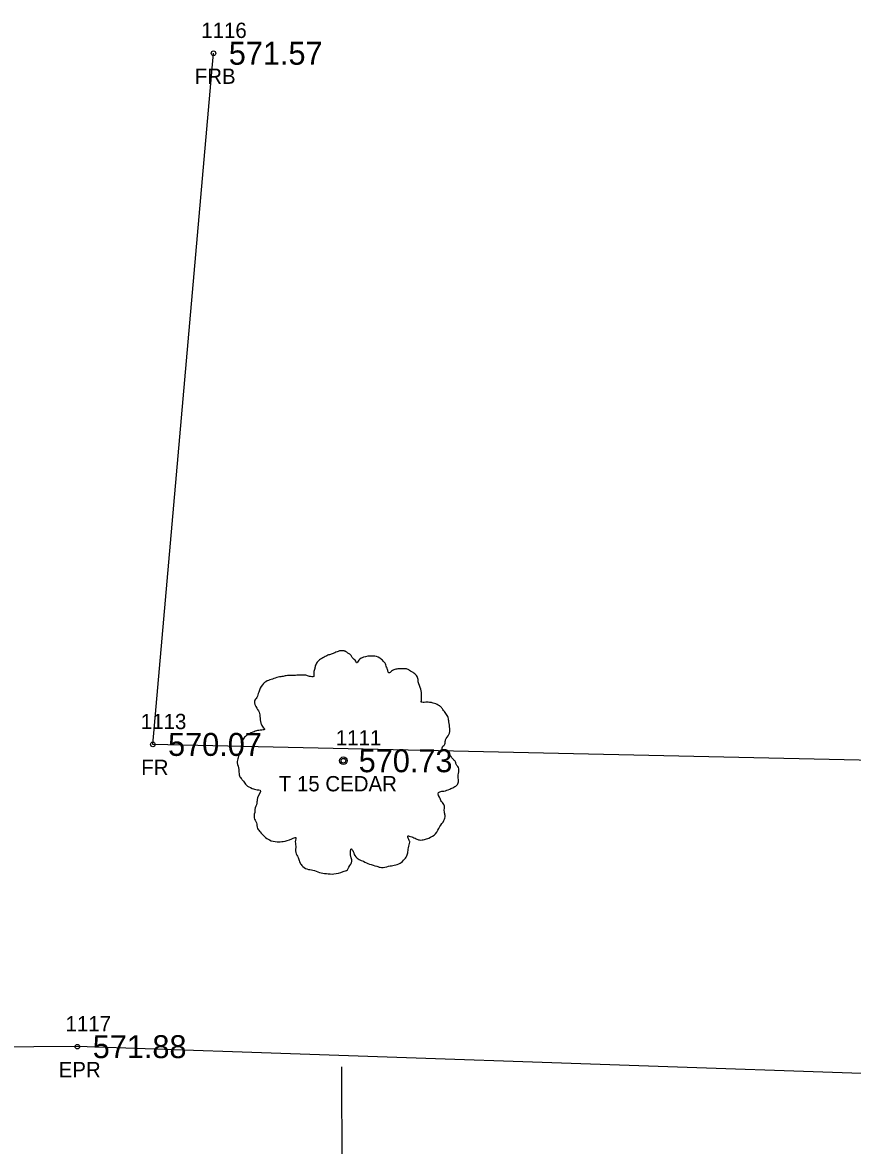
# Model space of a CAD drawing. Extents: x 1529475 to 1532053, y 876698 to 877911.
# Drawn here: x 1531129 to 1531183.3, y 877286.3 to 877359.7 of the extents above; entities that cross this region are included whole.
import ezdxf

# ---------------------------------------------------------------- set-up
doc = ezdxf.new("R2010")
doc.units = 0
for name, color, linetype in [('RD_EX_Fence_Other', 7, 'Continuous'), ('RD_EX_Fence_Other_txCode', 7, 'Continuous'), ('RD_EX_Road', 7, 'Continuous'), ('RD_EX_Road_txCode', 7, 'Continuous'), ('RD_EX_TX_Fence_Other_ELEV', 7, 'Continuous'), ('RD_EX_TX_Road_ELEV', 7, 'Continuous'), ('RD_EX_TX_VEG_ELEV', 7, 'Continuous'), ('RD_EX_VEG', 7, 'Continuous'), ('RD_EX_VEG_txCode', 7, 'Continuous'), ('RD_HC_Data_Tic', 7, 'Continuous'), ('RD_SMD_Locator', 7, 'Continuous')]:
    doc.layers.add(name, color=color, linetype=linetype)

msp = doc.modelspace()

# ---------------------------------------------------------------- linework, layer by layer
at = {"layer": 'RD_EX_Fence_Other'}
msp.add_lwpolyline([(1531287.683, 877345.243), (1531281.932, 877317.977), (1531278.086, 877303.259), (1531232.889, 877307.565), (1531185.71, 877311.458), (1531137.538, 877312.532), (1531141.511, 877357.73)], dxfattribs=at)
at = {"layer": 'RD_EX_Road'}
msp.add_lwpolyline([(1531606.641, 877133.837), (1531579.15, 877155.048), (1531564.866, 877165.268), (1531535.216, 877186.029), (1531511.532, 877200.27), (1531474.57, 877218.901), (1531430.451, 877239.347), (1531404.48, 877249.379), (1531382.323, 877256.431), (1531333.233, 877270.709), (1531303.666, 877277.444), (1531276.518, 877282.709), (1531237.324, 877287.202), (1531185.802, 877290.94), (1531132.609, 877292.767), (1531081.114, 877292.384), (1531038.69, 877288.667), (1530976.423, 877285.451), (1530941.057, 877284.256)], dxfattribs=at)
at = {"layer": 'RD_EX_VEG'}
for centre, radius in [((1531150.008, 877311.464), 0.25), ((1531149.996, 877311.445), 0.0001)]:
    msp.add_circle(centre, radius, dxfattribs=at)
for points in [[(1531150.14, 877318.631), (1531149.84, 877318.656), (1531149.515, 877318.556), (1531149.265, 877318.456), (1531149.041, 877318.381), (1531148.816, 877318.281), (1531148.516, 877318.107), (1531148.291, 877317.907), (1531148.166, 877317.657), (1531148.116, 877317.432), (1531148.066, 877317.157), (1531148.066, 877316.982), (1531147.941, 877316.957), (1531147.791, 877316.982), (1531147.541, 877317.057), (1531147.291, 877317.057), (1531147.041, 877317.057), (1531146.692, 877317.032), (1531146.342, 877317.032), (1531146.067, 877316.982), (1531145.742, 877316.932), (1531145.367, 877316.807), (1531145.017, 877316.682), (1531144.717, 877316.432), (1531144.468, 877315.957), (1531144.343, 877315.608), (1531144.193, 877315.358), (1531144.343, 877314.908), (1531144.518, 877314.558), (1531144.542, 877314.358), (1531144.617, 877313.933), (1531144.717, 877313.708), (1531144.842, 877313.508), (1531144.767, 877313.484), (1531144.393, 877313.434), (1531144.093, 877313.334), (1531143.668, 877313.109), (1531143.443, 877312.884), (1531143.343, 877312.559), (1531143.318, 877312.209), (1531143.218, 877312.009), (1531143.143, 877311.734), (1531143.118, 877311.659), (1531143.068, 877311.334), (1531143.168, 877310.885), (1531143.193, 877310.535), (1531143.318, 877310.31), (1531143.468, 877310.135), (1531143.643, 877309.885), (1531144.043, 877309.66), (1531144.368, 877309.56), (1531144.567, 877309.535), (1531144.393, 877309.035), (1531144.343, 877308.686), (1531144.218, 877308.286), (1531144.218, 877308.211), (1531144.168, 877307.736), (1531144.318, 877307.411), (1531144.393, 877307.036), (1531144.567, 877306.811), (1531144.842, 877306.512), (1531145.167, 877306.287), (1531145.667, 877306.162), (1531146.067, 877306.187), (1531146.642, 877306.362), (1531146.891, 877306.437), (1531146.866, 877306.262), (1531146.891, 877305.887), (1531146.891, 877305.462), (1531147.041, 877305.137), (1531147.141, 877304.862), (1531147.291, 877304.612), (1531147.616, 877304.388), (1531148.016, 877304.313), (1531148.441, 877304.163), (1531148.891, 877304.088), (1531149.39, 877304.063), (1531149.99, 877304.213), (1531150.265, 877304.338), (1531150.365, 877304.512), (1531150.565, 877304.887), (1531150.515, 877305.112), (1531150.54, 877305.712), (1531150.64, 877305.537), (1531150.815, 877305.187), (1531151.315, 877304.887), (1531151.714, 877304.712), (1531152.189, 877304.562), (1531152.489, 877304.487), (1531152.964, 877304.562), (1531153.339, 877304.637), (1531153.713, 877304.762), (1531154.013, 877305.037), (1531154.188, 877305.312), (1531154.238, 877305.587), (1531154.313, 877305.962), (1531154.363, 877306.137)], [(1531154.363, 877306.137), (1531154.288, 877306.312), (1531154.238, 877306.562), (1531154.313, 877306.537), (1531154.488, 877306.487), (1531154.763, 877306.362), (1531154.988, 877306.287), (1531155.313, 877306.312), (1531155.588, 877306.412), (1531156.037, 877306.687), (1531156.312, 877307.161), (1531156.587, 877307.561), (1531156.662, 877307.886), (1531156.612, 877308.111), (1531156.587, 877308.611), (1531156.387, 877308.861), (1531156.337, 877308.985), (1531156.237, 877309.385), (1531156.312, 877309.435), (1531156.587, 877309.485), (1531156.962, 877309.61), (1531157.237, 877309.735), (1531157.462, 877309.91), (1531157.537, 877310.135), (1531157.512, 877310.535), (1531157.562, 877310.935), (1531157.487, 877311.085), (1531157.387, 877311.234), (1531157.312, 877311.434), (1531157.162, 877311.584), (1531157.062, 877311.734), (1531156.962, 877311.834), (1531156.837, 877311.984), (1531156.662, 877312.109), (1531156.512, 877312.159), (1531156.462, 877312.309), (1531156.612, 877312.509), (1531156.662, 877312.609), (1531156.687, 877312.834), (1531156.912, 877313.184), (1531156.962, 877313.583), (1531156.912, 877314.008), (1531156.862, 877314.283), (1531156.712, 877314.558), (1531156.512, 877314.808), (1531156.387, 877314.983), (1531156.212, 877315.108), (1531155.888, 877315.233), (1531155.638, 877315.283), (1531155.288, 877315.283), (1531155.088, 877315.333), (1531155.113, 877315.383), (1531155.113, 877315.533), (1531155.113, 877315.808), (1531155.038, 877316.257), (1531154.888, 877316.757), (1531154.888, 877316.782), (1531154.788, 877317.032), (1531154.563, 877317.232), (1531154.388, 877317.332), (1531154.188, 877317.457), (1531153.938, 877317.482), (1531153.639, 877317.482), (1531153.364, 877317.432), (1531153.164, 877317.332), (1531152.989, 877317.207), (1531152.914, 877317.357), (1531152.814, 877317.657), (1531152.764, 877317.807), (1531152.614, 877317.982), (1531152.389, 877318.181), (1531151.939, 877318.306), (1531151.315, 877318.231), (1531151.015, 877318.032), (1531150.865, 877317.857), (1531150.815, 877317.982), (1531150.615, 877318.181), (1531150.515, 877318.356), (1531150.34, 877318.481), (1531150.19, 877318.581), (1531150.09, 877318.631)]]:
    msp.add_spline(points, degree=3, dxfattribs=at)
at = {"layer": 'RD_HC_Data_Tic'}
msp.add_line((1531149.935, 877283.441), (1531149.909, 877291.441), dxfattribs=at)
at = {"layer": 'RD_SMD_Locator'}
for centre in [(1531141.511, 877357.73), (1531137.538, 877312.532), (1531150.008, 877311.464), (1531132.609, 877292.767)]:
    msp.add_circle(centre, 0.15, dxfattribs=at)

# ---------------------------------------------------------------- texts
at = {"layer": 'RD_EX_Fence_Other_txCode'}
for s, p in [('1116', (1531140.708, 877358.73)), ('FRB', (1531140.283, 877355.73)), ('1113', (1531136.758, 877313.532)), ('FR', (1531136.782, 877310.532))]:
    msp.add_text(s, height=1, dxfattribs=at).set_placement(p)
at = {"layer": 'RD_EX_Road_txCode'}
for s, p in [('1117', (1531131.83, 877293.767)), ('EPR', (1531131.381, 877290.767))]:
    msp.add_text(s, height=1, dxfattribs=at).set_placement(p)
at = {"layer": 'RD_EX_TX_Fence_Other_ELEV'}
for s, p in [('571.57', (1531142.511, 877356.98)), ('570.07', (1531138.538, 877311.782))]:
    msp.add_text(s, height=1.5, dxfattribs=at).set_placement(p)
at = {"layer": 'RD_EX_TX_Road_ELEV'}
msp.add_text('571.88', height=1.5, dxfattribs=at).set_placement((1531133.609, 877292.017))
at = {"layer": 'RD_EX_TX_VEG_ELEV'}
msp.add_text('570.73', height=1.5, dxfattribs=at).set_placement((1531151.008, 877310.714))
at = {"layer": 'RD_EX_VEG_txCode'}
for s, p in [('1111', (1531149.512, 877312.464)), ('T 15 CEDAR', (1531145.78, 877309.464))]:
    msp.add_text(s, height=1, dxfattribs=at).set_placement(p)

doc.saveas('drawing.dxf')
